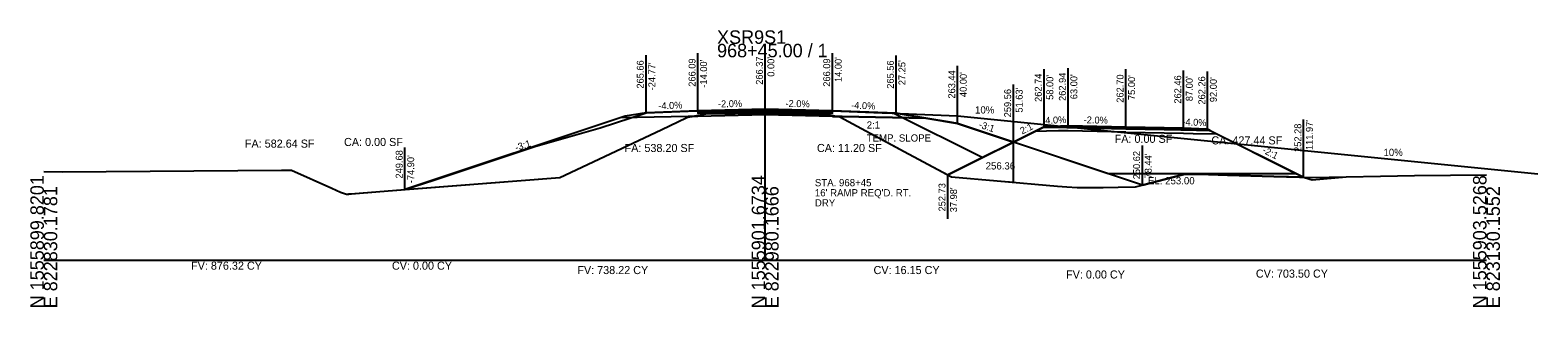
# Model space of a CAD drawing. Extents: x -26 to 823017, y -16 to 1558356.
# Drawn here: x 997.2 to 1310.7, y 8490.3 to 8547.8 of the extents above; entities that cross this region are included whole.
import ezdxf

# ---------------------------------------------------------------- set-up
doc = ezdxf.new("R2010")
doc.units = 0
for name, color, linetype in [('1', 7, 'Continuous'), ('ASPHALT_19MM1', 7, 'Continuous'), ('ASPHALT_9_5MM1', 7, 'Continuous'), ('CONST_DCH', 7, 'Continuous'), ('CONST_LV3', 7, 'Continuous'), ('Draft_XS_Grid', 7, 'Continuous'), ('DTM_CORRIDOR', 7, 'Continuous'), ('DTM_P_FINISHED_GRADE2', 7, 'Continuous'), ('DTM_X_GROUND', 7, 'Continuous'), ('SLOPE_STAKES_FILL', 7, 'Continuous'), ('X_PROFILES_1', 7, 'Continuous'), ('X_TRANS_EOP', 7, 'Continuous'), ('XS_CELL', 7, 'Continuous'), ('XS_M_SHAPES_EARTHWORK', 7, 'Continuous'), ('XS_P_DR_GRAVEL', 7, 'Continuous'), ('XS_P_DRIVEWAY', 7, 'Continuous'), ('XS_P_GROUND', 7, 'Continuous'), ('XS_P_NULL_POINT', 7, 'Continuous'), ('XS_P_SHOULDER', 7, 'Continuous'), ('XS_P_SUBGRADE_GRANULAR', 7, 'Continuous'), ('XS_P_SUBGRADE_UNDERCUT', 7, 'Continuous'), ('XS_P_TX_CLEARZONE', 7, 'Continuous'), ('XS_P_TX_FS_BS', 7, 'Continuous'), ('XS_SHEET_EW_TX_AREA', 7, 'Continuous'), ('XS_SHEET_EW_TX_VOLUME', 7, 'Continuous')]:
    doc.layers.add(name, color=color, linetype=linetype)

msp = doc.modelspace()

# ---------------------------------------------------------------- linework, layer by layer
at = {"layer": '1'}
msp.add_lwpolyline([(1136, 8530.93), (1136, 8530.8), (1147.2, 8531.02), (1150, 8531.08), (1152.8, 8531.02), (1164, 8530.8), (1164, 8530.93), (1164, 8530.97), (1152.8, 8531.19), (1150, 8531.25), (1147.2, 8531.19), (1136, 8530.97), (1136, 8530.93)], dxfattribs=at)
at = {"layer": 'ASPHALT_19MM1'}
for points in [[(1136, 8530.76), (1136, 8530.59), (1147.2, 8530.81), (1150, 8530.87), (1152.8, 8530.81), (1164, 8530.59), (1164, 8530.76), (1164, 8530.8), (1152.8, 8531.02), (1150, 8531.08), (1147.2, 8531.02), (1136, 8530.8), (1136, 8530.76)], [(1213, 8527.57), (1225, 8527.33), (1237, 8527.09), (1237, 8527.29), (1225, 8527.53), (1213, 8527.77), (1213, 8527.57)]]:
    msp.add_lwpolyline(points, dxfattribs=at)
at = {"layer": 'ASPHALT_9_5MM1'}
msp.add_lwpolyline([(1136, 8531.07), (1136, 8530.97), (1147.2, 8531.19), (1150, 8531.25), (1152.8, 8531.19), (1164, 8530.97), (1164, 8531.07), (1164, 8531.09), (1152.8, 8531.31), (1150, 8531.37), (1147.2, 8531.31), (1136, 8531.09), (1136, 8531.07)], dxfattribs=at)
at = {"layer": 'CONST_LV3'}
for points in [[(1150, 8531.37), (1164, 8531.09)], [(1177.25, 8530.56), (1177.25, 8530.56), (1164, 8531.09)], [(1190, 8528.44), (1188.91, 8528.62), (1183.4, 8529.54)], [(1187.98, 8517.73), (1188.97, 8518.22), (1208, 8527.74), (1208.25, 8527.75), (1213, 8527.94)], [(1201.63, 8524.56), (1206.73, 8527.1), (1208, 8527.74), (1208.25, 8527.75), (1213, 8527.94), (1224.41, 8527.71), (1225, 8527.7), (1236.41, 8527.12), (1237, 8527.09), (1237.25, 8527.09), (1242, 8527.26), (1260.96, 8517.78), (1262.18, 8517.17), (1263.74, 8516.74), (1270.84, 8517.37), (1277.94, 8517.51), (1285.05, 8517.64), (1300, 8517.73)], [(1242, 8527.26), (1261.97, 8517.28)], [(1000, 8518.42), (1003.87, 8518.38), (1049.43, 8518.73), (1051.49, 8518.72), (1059.89, 8514.96), (1061.67, 8514.17), (1062.97, 8513.71), (1063.44, 8513.76), (1063.86, 8513.81), (1064, 8513.82), (1065.66, 8513.95), (1071.61, 8514.4), (1075.1, 8514.68)]]:
    msp.add_lwpolyline(points, dxfattribs=at)
at = {"layer": 'DTM_P_FINISHED_GRADE2'}
msp.add_lwpolyline([(1075.1, 8514.68), (1102.12, 8523.68), (1115.72, 8527.52), (1125.23, 8530.66), (1133.98, 8531.01), (1136, 8531.09), (1138.8, 8531.15), (1150, 8531.37), (1161.2, 8531.15), (1164, 8531.09), (1174.34, 8530.68), (1177.25, 8530.56), (1187.72, 8528.82), (1190, 8528.44), (1199.24, 8525.36), (1201.63, 8524.56)], dxfattribs=at)
at = {"layer": 'DTM_X_GROUND'}
for points in [[(1000, 8518.42), (1003.87, 8518.38), (1049.43, 8518.73), (1051.49, 8518.72), (1059.89, 8514.96), (1061.67, 8514.17), (1062.97, 8513.71), (1063.44, 8513.8), (1063.86, 8513.82), (1064, 8513.82), (1065.66, 8513.95), (1071.61, 8514.41), (1075.1, 8514.68), (1081.1, 8516.68), (1087.56, 8518.83), (1102.12, 8523.68), (1115.72, 8527.52), (1125.23, 8530.66), (1133.98, 8531.01), (1136, 8531.09), (1138.8, 8531.15), (1150, 8531.37), (1161.2, 8531.15), (1164, 8531.09), (1174.34, 8530.68), (1177.25, 8530.56), (1187.72, 8528.82), (1190, 8528.44), (1199.24, 8525.36), (1201.63, 8524.56), (1206.73, 8527.1), (1208, 8527.74), (1208.25, 8527.75), (1213, 8527.94), (1224.41, 8527.71), (1225, 8527.7), (1236.41, 8527.12), (1237, 8527.09), (1237.25, 8527.09), (1242, 8527.26), (1260.96, 8517.78), (1262.18, 8517.17), (1263.74, 8516.74), (1270.84, 8517.37), (1277.94, 8517.51), (1285.05, 8517.64), (1300, 8517.73)], [(1000, 8518.42), (1003.87, 8518.38), (1049.43, 8518.73), (1051.49, 8518.72), (1059.89, 8514.96), (1061.67, 8514.17), (1062.97, 8513.71), (1063.86, 8513.81), (1071.61, 8514.4), (1107.31, 8517.21), (1128.38, 8527.12), (1133.7, 8529.65), (1134.63, 8529.86), (1137.69, 8530.43), (1143.75, 8530.5), (1150.5, 8530.58), (1157.59, 8530.43), (1163.19, 8530.31), (1164.74, 8529.98), (1165.52, 8529.81), (1178.93, 8522.61), (1188.73, 8517.34), (1198.24, 8516.5), (1210.76, 8515.41), (1212.71, 8515.24), (1214.89, 8515.1), (1220.3, 8515.15), (1223.43, 8515.2), (1227.04, 8515.26), (1236.47, 8517.7), (1237.4, 8517.93), (1242.21, 8517.81), (1246.13, 8517.71), (1255.79, 8517.43), (1263.74, 8517.23), (1270.84, 8517.37), (1277.94, 8517.51), (1285.05, 8517.64), (1300, 8517.73)], [(1000, 8518.42), (1003.87, 8518.38), (1049.43, 8518.73), (1051.49, 8518.72), (1059.89, 8514.96), (1061.67, 8514.17), (1062.97, 8513.71), (1063.86, 8513.81), (1071.61, 8514.4), (1107.31, 8517.21), (1128.38, 8527.12), (1133.7, 8529.65), (1134.63, 8529.86), (1137.69, 8530.43), (1143.75, 8530.5), (1150.5, 8530.58), (1157.59, 8530.43), (1163.19, 8530.31), (1164.74, 8529.98), (1165.52, 8529.81), (1177.38, 8523.43), (1178.93, 8522.6), (1187.98, 8517.73), (1188.97, 8518.22), (1208, 8527.74), (1208.25, 8527.75), (1213, 8527.94), (1224.41, 8527.71), (1225, 8527.7), (1236.41, 8527.12), (1237, 8527.09), (1237.25, 8527.09), (1242, 8527.26), (1260.96, 8517.78), (1262.18, 8517.17), (1263.74, 8516.74), (1270.84, 8517.37), (1277.94, 8517.51), (1285.05, 8517.64), (1300, 8517.73)]]:
    msp.add_lwpolyline(points, dxfattribs=at)
at = {"layer": 'X_TRANS_EOP'}
msp.add_lwpolyline([(1213, 8527.77), (1225, 8527.53), (1237, 8527.29), (1237, 8527.46), (1225, 8527.7), (1213, 8527.94), (1213, 8527.77)], dxfattribs=at)
at = {"layer": 'XS_CELL'}
for p, q in [((1150, 8500), (1150, 8545)), ((1000, 8500), (1150, 8500)), ((1150, 8500), (1300, 8500))]:
    msp.add_line(p, q, dxfattribs=at)
at = {"layer": 'XS_M_SHAPES_EARTHWORK'}
for points in [[(1075.1, 8514.68), (1107.31, 8517.21), (1128.38, 8527.12), (1133.7, 8529.65), (1134.63, 8529.86), (1134.85, 8529.9), (1134, 8529.88), (1119.88, 8529.6), (1075.1, 8514.68)], [(1134.85, 8529.9), (1137.69, 8530.43), (1143.75, 8530.5), (1150.5, 8530.58), (1157.59, 8530.43), (1163.19, 8530.31), (1164.74, 8529.98), (1165.08, 8529.9), (1164, 8529.92), (1152.8, 8530.15), (1150, 8530.2), (1136, 8529.92)], [(1165.08, 8529.9), (1165.52, 8529.81), (1178.93, 8522.61), (1188.73, 8517.34), (1198.24, 8516.5), (1201.63, 8516.21), (1201.63, 8524.56), (1190, 8528.44), (1183.4, 8529.54), (1166, 8529.88)]]:
    msp.add_lwpolyline(points, close=True, dxfattribs=at)
at = {"layer": 'XS_P_DR_GRAVEL'}
for points in [[(1208.25, 8527.75), (1208, 8527.74), (1207.86, 8527.67), (1207.86, 8527.67), (1212.75, 8527.57), (1213, 8527.57), (1213, 8527.58), (1213, 8527.94), (1208.25, 8527.75)], [(1241.75, 8527.27), (1237, 8527.46), (1237, 8527.1), (1237, 8527.09), (1242.3, 8526.98), (1242.57, 8526.97), (1242.54, 8526.99), (1242, 8527.26), (1241.75, 8527.27)]]:
    msp.add_lwpolyline(points, dxfattribs=at)
at = {"layer": 'XS_P_DRIVEWAY'}
for p, q in [((1174.66, 8530.66), (1190, 8530.05)), ((1190, 8530.05), (1310.68, 8517.98))]:
    msp.add_line(p, q, dxfattribs=at)
at = {"layer": 'XS_P_GROUND'}
msp.add_line((1176.92, 8530.53), (1195.26, 8521.36), dxfattribs=at)
for points in [[(1125.23, 8530.66), (1120.88, 8529.93), (1075.1, 8514.68)], [(1177.25, 8530.56), (1190, 8528.44), (1201.63, 8524.56)], [(1228.44, 8515.62), (1190, 8528.44), (1190, 8528.44), (1190, 8528.44), (1177.25, 8530.56)], [(1208, 8527.74), (1187.98, 8517.73)], [(1242, 8527.26), (1262.18, 8517.17)], [(1255.79, 8517.43), (1246.13, 8517.71), (1246.13, 8517.71), (1242.21, 8517.81), (1237.4, 8517.93), (1237.4, 8517.93), (1236.47, 8517.7), (1236.47, 8517.7), (1228.44, 8515.62), (1228.44, 8515.62), (1228.44, 8515.62), (1228.44, 8515.62), (1236.47, 8517.7), (1236.47, 8517.7), (1237.4, 8517.93), (1237.4, 8517.93), (1242.21, 8517.81), (1246.13, 8517.71), (1246.13, 8517.71), (1255.79, 8517.43), (1261.97, 8517.28), (1261.97, 8517.28), (1261.97, 8517.28), (1261.97, 8517.28), (1255.79, 8517.43)]]:
    msp.add_lwpolyline(points, dxfattribs=at)
at = {"layer": 'XS_P_SHOULDER'}
for points in [[(1136, 8531.09), (1125.23, 8530.66)], [(1164, 8531.09), (1177.25, 8530.56)], [(1208, 8527.74), (1208.25, 8527.75), (1213, 8527.94)], [(1242, 8527.26), (1241.75, 8527.27), (1237, 8527.46)]]:
    msp.add_lwpolyline(points, dxfattribs=at)
at = {"layer": 'XS_P_SUBGRADE_GRANULAR'}
for points in [[(1136, 8529.92), (1134, 8529.88), (1119.88, 8529.6)], [(1150, 8530.2), (1136, 8529.92)], [(1164, 8529.92), (1152.8, 8530.15), (1150, 8530.2)], [(1164, 8529.92), (1166, 8529.88), (1183.4, 8529.54)], [(1213, 8526.9), (1211, 8526.94), (1206, 8526.74)], [(1225, 8526.66), (1213, 8526.9)], [(1225, 8526.66), (1237, 8526.42)], [(1237, 8526.42), (1239, 8526.38), (1243.96, 8526.28)]]:
    msp.add_lwpolyline(points, dxfattribs=at)
at = {"layer": 'XS_P_SUBGRADE_UNDERCUT'}
msp.add_lwpolyline([(1221.31, 8518), (1201.63, 8524.56), (1208, 8527.73), (1213, 8527.93), (1225, 8527.69), (1237, 8527.45), (1242, 8527.25), (1260.5, 8518)], close=True, dxfattribs=at)
at = {"layer": 'XS_P_TX_CLEARZONE'}
for p, q in [((1125.23, 8530.66), (1125.23, 8542.66)), ((1136, 8531.09), (1136, 8543.09)), ((1150, 8531.37), (1150, 8543.37)), ((1164, 8531.09), (1164, 8543.09)), ((1177.25, 8530.56), (1177.25, 8542.56)), ((1190, 8528.44), (1190, 8540.44)), ((1190, 8528.44), (1190, 8540.44)), ((1208, 8527.74), (1208, 8539.74)), ((1213, 8527.94), (1213, 8539.94)), ((1225, 8527.7), (1225, 8539.7)), ((1237, 8527.46), (1237, 8539.46)), ((1242, 8527.26), (1242, 8539.26)), ((1201.63, 8524.56), (1201.63, 8536.56)), ((1261.97, 8517.28), (1261.97, 8529.28)), ((1075.1, 8514.68), (1075.1, 8523.47)), ((1228.44, 8515.62), (1228.44, 8523.89)), ((1187.98, 8508.61), (1187.98, 8517.73))]:
    msp.add_line(p, q, dxfattribs=at)

# ---------------------------------------------------------------- texts
at = {"layer": 'CONST_DCH'}
for p in [(1135.92, 8530.97), (1149.92, 8531.25), (1163.92, 8530.97)]:
    msp.add_text('X', height=0.24, dxfattribs=at).set_placement(p)
at = {"layer": 'CONST_LV3'}
for p in [(1177.17, 8530.44), (1189.92, 8528.32), (1201.55, 8524.44), (1228.36, 8515.5), (1261.89, 8517.16), (1075.02, 8514.56)]:
    msp.add_text('X', height=0.24, dxfattribs=at).set_placement(p)
at = {"layer": 'Draft_XS_Grid'}
msp.add_text('-', height=0.0001, dxfattribs=at).set_placement((1000, 8500))
at = {"layer": 'DTM_CORRIDOR'}
for p in [(1212.92, 8527.82), (1224.92, 8527.58), (1236.92, 8527.34)]:
    msp.add_text('X', height=0.24, dxfattribs=at).set_placement(p)
at = {"layer": 'SLOPE_STAKES_FILL'}
for p in [(1187.9, 8517.61), (1262.1, 8517.05)]:
    msp.add_text('X', height=0.24, dxfattribs=at).set_placement(p)
at = {"layer": 'X_PROFILES_1'}
msp.add_text('X', height=0.24, dxfattribs=at).set_placement((1261.89, 8517.16))
at = {"layer": 'XS_CELL'}
for s, p in [('XSR9S1', (1140, 8545)), ('968+45.00 / 1', (1140, 8542.2))]:
    msp.add_text(s, height=2.8, dxfattribs=at).set_placement(p)
for s, p in [('N 1555899.8201', (1000, 8490)), ('N 1555901.6734', (1150, 8490)), ('N 1555903.5268', (1300, 8490)), ('E 822830.1781', (1002.8, 8490)), ('E 822980.1666', (1152.8, 8490)), ('E 823130.1552', (1302.8, 8490))]:
    msp.add_text(s, height=2.8, rotation=90, dxfattribs=at).set_placement(p)
at = {"layer": 'XS_P_DRIVEWAY'}
for s, p in [('10%', (1193.65, 8530.51)), ('10%', (1278.58, 8521.68)), ('STA. 968+45', (1160.34, 8515.38)), ("16' RAMP REQ'D. RT.", (1160.34, 8513.28)), ('DRY', (1160.34, 8511.18))]:
    msp.add_text(s, height=1.5, dxfattribs=at).set_placement(p)
at = {"layer": 'XS_P_GROUND'}
for s, p in [('2:1', (1171.12, 8527.37)), ('TEMP. SLOPE', (1171.12, 8524.67)), ('256.36', (1195.85, 8518.87))]:
    msp.add_text(s, height=1.5, dxfattribs=at).set_placement(p)
at = {"layer": 'XS_P_NULL_POINT'}
for p in [(1201.55, 8524.44), (1187.9, 8517.61), (1262.1, 8517.05), (1075.02, 8514.56)]:
    msp.add_text('X', height=0.24, dxfattribs=at).set_placement(p)
at = {"layer": 'XS_P_SHOULDER'}
for p in [(1125.15, 8530.54), (1177.17, 8530.44), (1207.92, 8527.62), (1241.92, 8527.14)]:
    msp.add_text('X', height=0.24, dxfattribs=at).set_placement(p)
at = {"layer": 'XS_P_SUBGRADE_GRANULAR'}
msp.add_text('X', height=0.24, dxfattribs=at).set_placement((1189.92, 8528.32))
at = {"layer": 'XS_P_SUBGRADE_UNDERCUT'}
msp.add_text('EL. 253.00', height=1.5, dxfattribs=at).set_placement((1229.61, 8515.79))
at = {"layer": 'XS_P_TX_CLEARZONE'}
for s, p in [('265.66', (1124.75, 8535.69)), ("-24.77'", (1127.15, 8535.32)), ('266.09', (1135.52, 8536.08)), ("-14.00'", (1137.92, 8535.88)), ('266.37', (1149.52, 8536.48)), ("0.00'", (1151.92, 8538.16)), ('266.09', (1163.52, 8536.08)), ("14.00'", (1165.92, 8537.06)), ('265.56', (1176.77, 8535.66)), ("27.25'", (1179.17, 8536.4)), ('263.44', (1189.52, 8533.61)), ("40.00'", (1191.92, 8533.93)), ('262.74', (1207.52, 8532.92)), ("58.00'", (1209.92, 8533.35)), ('262.94', (1212.52, 8533.12)), ("63.00'", (1214.92, 8533.48)), ('262.70', (1224.52, 8532.75)), ("75.00'", (1226.92, 8533.31)), ('262.46', (1236.52, 8532.56)), ("87.00'", (1238.92, 8533.07)), ('262.26', (1241.52, 8532.36)), ("92.00'", (1243.92, 8532.87)), ('259.56', (1201.15, 8529.72)), ("51.63'", (1203.55, 8530.69)), ('252.28', (1261.49, 8522.52)), ("111.97'", (1263.89, 8522.91)), ('249.68', (1074.62, 8516.99)), ("-74.90'", (1077.02, 8516.01)), ('250.62', (1227.96, 8516.83)), ("78.44'", (1230.36, 8517.01)), ('252.73', (1187.5, 8510.14)), ("37.98'", (1189.9, 8509.97))]:
    msp.add_text(s, height=1.44, rotation=90, dxfattribs=at).set_placement(p)
at = {"layer": 'XS_P_TX_FS_BS'}
for s, rotation, p in [('-4.0%', 2.2906, (1127.8, 8531.36)), ('-2.0%', 1.1458, (1140.2, 8531.78)), ('-2.0%', 358.8542, (1154.22, 8531.89)), ('-4.0%', 357.7094, (1167.86, 8531.54)), ('-3:1', 341.5668, (1194.29, 8527.64)), ('2:1', 26.559, (1203.45, 8526.14)), ('4.0%', 2.2906, (1208.27, 8528.35)), ('-2.0%', 358.8542, (1216.22, 8528.48)), ('-4.0%', 357.7094, (1236.73, 8528.07)), ('-3:1', 17.6844, (1098.25, 8522.69)), ('-2:1', 333.4344, (1253.27, 8522.44))]:
    msp.add_text(s, height=1.44, rotation=rotation, dxfattribs=at).set_placement(p)
at = {"layer": 'XS_SHEET_EW_TX_AREA'}
for s, p in [('FA: 582.64 SF', (1041.81, 8523.41)), ('CA: 0.00 SF', (1062.43, 8523.75)), ('FA: 0.00 SF', (1222.68, 8524.41)), ('CA: 427.44 SF', (1242.8, 8524.08)), ('FA: 538.20 SF', (1120.77, 8522.5)), ('CA: 11.20 SF', (1160.77, 8522.5))]:
    msp.add_text(s, height=1.68, dxfattribs=at).set_placement(p)
at = {"layer": 'XS_SHEET_EW_TX_VOLUME'}
for s, p in [('FV: 876.32 CY', (1030.62, 8498.03)), ('CV: 0.00 CY', (1072.39, 8498.03)), ('FV: 738.22 CY', (1110.95, 8497.12)), ('CV: 16.15 CY', (1172.54, 8497.12)), ('FV: 0.00 CY', (1212.58, 8496.2)), ('CV: 703.50 CY', (1252.05, 8496.38))]:
    msp.add_text(s, height=1.68, dxfattribs=at).set_placement(p)

doc.saveas('drawing.dxf')
